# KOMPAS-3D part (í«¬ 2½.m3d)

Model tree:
1. Эскиз:1
2. Операция выдавливания:1
     Расстояние 1 = 3
3. Эскиз:2
4. Операция выдавливания:2
     Расстояние 1 = 78
5. Эскиз:3
6. Операция выдавливания:3
     Расстояние 1 = 3
7. Эскиз:4
8. Операция выдавливания:4
     Расстояние 1 = 4
9. Эскиз:5
10. Операция выдавливания:5
     Расстояние 1 = 4
11. Эскиз:6
12. Вырезать элемент выдавливания:1
     Расстояние 2 = 110; Расстояние 1 = 100
